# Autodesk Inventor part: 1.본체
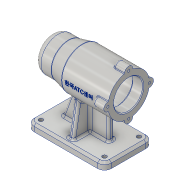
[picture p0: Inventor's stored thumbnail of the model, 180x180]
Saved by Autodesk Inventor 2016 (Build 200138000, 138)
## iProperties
Created: 2019-07
Part Number: 1.본체
Material: 알루미늄 6061
Document SubType Name: Modeling
Designer: 605-08
Density: 2.7 g/cm^3
Appearance: 알루미늄 - 평지
Mass: 644.389 g
Surface Area: 654.079 cm^2
Volume: 238.663 cm^3
Author: 605-08
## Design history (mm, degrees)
sketch "스케치1"
  geometry: L1 (-56, 0)-(56, 0); L2 (56, 21)-(41, 21); L3 (41, 21)-(41, 24); L4 (41, 24)-(-13, 24); L5 (-13, 24)-(-13, 21); L6 (-13, 21)-(-25, 21); L7 (-25, 21)-(-25, 17.5); L8 (-25, 17.5)-(-43, 17.5); L9 (-43, 17.5)-(-43, 16); L10 (-43, 16)-(-47, 16); L11 (-47, 16)-(-47, 10.5); L12 (56, 21)-(56, 30); L13 (56, 30)-(-11, 30); L14 (-11, 30)-(-31, 25); L15 (-31, 25)-(-56, 25); L16 (-56, 25)-(-56, 0); L17 (-47, 10.5)-(-50, 10.5); L18 (-50, 10.5)-(-50, 0); L19 (-56, 0)-(-50, 0); 1 further point
  constraints: 38 end point, 10 perpendicular, 5 horizontal, 1 collinear, 1 midpoint, 1 parallel, 1 point on line, 1 vertical, 1 vertical alignment
  dimensions: "d0" = 112 distance of L1.start L1.end; "d2" = 56 distance of L1.start point (0, 0); "d3" = 42 diameter of L2 L1; "d4" = 48 diameter of L4 L1; "d5" = 42 diameter of L6 L1; "d6" = 21 diameter of L17 L1; "d7" = 32 diameter of L10 L1; "d8" = 35 diameter of L8 L1; "d9" = 50 diameter of L15 L1; "d10" = 60 diameter of L13 L1; "d11" = 45 distance from line of L16 L13.end; "d12" = 25 distance of L14.end L15.end; "d13" = 15 distance of L2.start L2.end; "d14" = 54 distance of L3.end L4.end; "d15" = 12 distance of L5.end L6.end; "d16" = 18 distance of L7.end L8.end; "d17" = 3 distance of L11.end L17.end; "d18" = 4 distance of L9.end L10.end
revolve "회전1" sketch "스케치1" stored, may be unused: angle "d19" = 90 deg
sketch "스케치2"
  geometry: L1 (-56, -70)-(56, -70); L2 (56, -70)-(56, -80); L3 (56, -80)-(-56, -80); L4 (-56, -80)-(-56, -70); 2 further points
  constraints: 8 end point, 2 parallel, 1 horizontal, 1 midpoint, 1 perpendicular, 1 vertical alignment
  dimensions: "d20" = 112 distance of L2.end L3.end; "d21" = 10 distance of L1.end L2.end; "d22" = 80 distance from line of point (0, 0) L3
extrude "돌출1" join sketch "스케치2" stored distance "d23" = 70; taper "d24" = 0 deg
sketch "스케치3"
  geometry: L1 (-80, 35)-(-80, -35) reference; L2 (-70, 35)-(-80, 35) reference; L3 (-70, -35)-(-70, 35) reference; L4 (-80, -35)-(-70, -35) reference; L5 (-70, -35)-(-70, 35) reference; L6 (-70, -28)-(-22.666, -19.654); L7 (-22.666, 19.654)-(-70, 28); A1 r 30 centre (0, 0) between (-22.666, -19.654) and (-22.666, 19.654) reference; 1 further point
  constraints: 4 end point, 2 point on circle, 2 point on line
  dimensions: "d25" = 100 deg angle of L3 L6; "d26" = 100 deg angle of L3 L7; "d27" = 7 distance of L3.start L6.start; "d28" = 7 distance of L2.start L7.end
extrude "돌출2" join sketch "스케치3" stored distance "d29" = 8; taper "d30" = 0 deg
sketch "스케치4"
  geometry: L1 (31, -29.936)-(31, -70); L2 (-56, -70)-(56, -70) reference; L3 (-36, -70)-(-20.57, -27.607); L4 (-31, -25)-(-11, -30) reference; L5 (-11, -30)-(56, -30) reference; 1 further point
  constraints: 4 end point, 3 point on line, 1 vertical
  dimensions: "d31" = 110 deg angle of L2 L3; "d32" = 90 deg angle of L2 L1 (derived); "d33" = 25 distance of L2.end L1.end; "d34" = 20 distance of L3.start L2.start
feature "리브1" sketch "스케치4" dims "d35" = 1, "d36" = 8, "d37" = 0, "d38" = 0, "d39" = 1, "d40" = 1
sketch "스케치5"
  geometry: L1 (31, -30)-(31, -70); L2 (-56, -70)-(56, -70) reference; L3 (4, -30)-(56, -30) reference; L4 (56, -80)-(56, -70) reference; 1 further point
  constraints: 2 end point, 2 point on line, 1 perpendicular
  dimensions: "d93" = 25 distance between parallel lines of L4 L1
feature "리브2" sketch "스케치5" dims "d41" = 1, "d42" = 8, "d43" = 0, "d44" = 0, "d45" = 1, "d46" = 1
sketch "스케치6"
  geometry: C1 r 21 at (0, 0) reference; C2 r 6 at (0, 30); 2 further points
  constraints: 1 centre point, 1 vertical alignment, 1 other
  dimensions: "d47" = 6 radius of C2
extrude "돌출3" join sketch "스케치6" distance "d48" = 16; taper "d49" = 0 deg
hole "구멍1" diameter "d52" = 3.242; stored, may be unused: countersink angle "d56" = 90 deg, drill point angle "d58" = 120 deg; dims "d53" = 8, "d54" = 4, "d55" = 2, "d57" = 11, "d94" = 10, "d95" = 10
sketch "스케치7"
  geometry: L1 (0, 0)-(0, 70) reference; L2 (112, 70)-(0, 70) reference; L3 (112, 0)-(112, 70) reference; L4 (0, 0)-(112, 0) reference; L5 (10, 60)-(10, 10); L6 (10, 10)-(102, 10); L7 (102, 10)-(102, 60); L8 (102, 60)-(10, 60); C1 r 3 at (10, 60); 1 further point
  constraints: 8 end point, 1 centre point, 1 coincident, 3 other
  dimensions: "d62" = 10 distance between parallel lines of L2 L8; "d63" = 6 diameter of C1
extrude "돌출4" cut sketch "스케치7" stored distance "d64" = 16; taper "d65" = 0 deg
fillet "모깎기1" dims "d72" = 10
fillet "모깎기2" dims "d73" = 10, "d74" = 3
fillet "모깎기3" dims "d75" = 1
fillet "모깎기4" dims "d76" = 3
chamfer "모따기1" distance "d77" = 1; stored, may be unused: second distance "d78" = 2, angle "d79" = 45 deg
fillet "모깎기5" dims "d80" = 0.3
fillet "모깎기6" dims "d81" = 3
fillet "모깎기7" dims "d82" = 3
chamfer "모따기2" distance "d85" = 3; stored, may be unused: second distance "d86" = 2, angle "d87" = 45 deg
node "작업 평면2"
sketch "스케치8"
  geometry: L1 (56, 36)-(56, 30.171) reference; 2 further points
  constraints: 1 horizontal alignment, 1 other
  dimensions: "d89" = 42 distance from line of L1 point (14, 0)
feature "엠보싱1" sketch "스케치8" dims "d90" = 0.5, "d91" = 0
fillet "모깎기10" dims "d92" = 3
fillet "모깎기11" dims "d96" = 3
node "솔리드1"
pattern_circular "원형 패턴1" dims angle "d60" = 360 deg
pattern_linear "직사각형 패턴1" dims "d68" = 50, "d71" = 92
node "투영된 루프1"
node "투영된 루프2"
node "투영된 루프3"
other parameters: "d88" = 30.5
